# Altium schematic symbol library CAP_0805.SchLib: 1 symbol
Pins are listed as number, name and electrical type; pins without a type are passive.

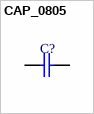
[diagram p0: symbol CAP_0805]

## CAP_0805
designator C?
footprint CAP_0805
pins: 1, 2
